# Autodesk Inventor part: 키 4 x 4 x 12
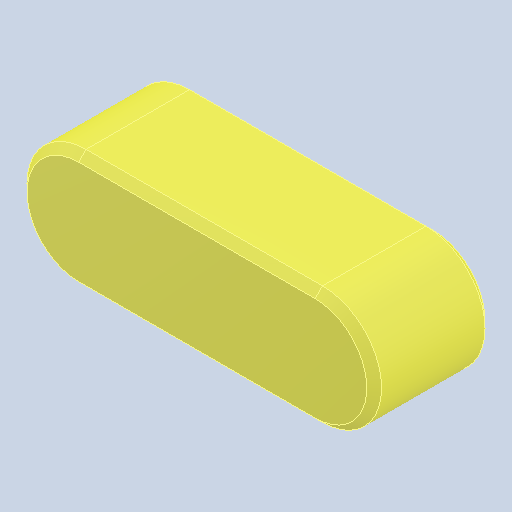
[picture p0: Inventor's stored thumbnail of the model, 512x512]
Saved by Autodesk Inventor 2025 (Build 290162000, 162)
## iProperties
Created: 2024-07
Part Number: 키 4 x 4 x 12
Material: 강철, 연강
Description: 키 및 해당 키홈
Document SubType Name: Modeling
Designer: samsung
Density: 7.85 g/cm^3
Appearance: 기본값
Author: jhkim
Sending System: Autodesk Inventor 2025
Preprocessor: ST-DEVELOPER v20
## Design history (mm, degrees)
feature "Solid1"
node "솔리드1"
